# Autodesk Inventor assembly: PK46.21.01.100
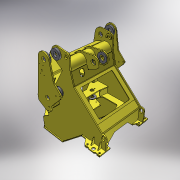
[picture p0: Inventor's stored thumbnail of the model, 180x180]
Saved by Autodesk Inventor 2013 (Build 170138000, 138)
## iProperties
Created: 2005-04
Part Number: PK46.21.01.100
Document SubType Name: Assembly
Designer: salex
Manufacturer: Standard
Standards Organization: Custom
Author: salex
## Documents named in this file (20)
- C:\Product Design Suite 2013 Test Drive\Dynamic Simulation\Workspace\Assy, Chassis, Front\PK46.21.01.100.iam
- C:\Product Design Suite 2013 Test Drive\Dynamic Simulation\Workspace\Assy, Chassis, Front\PK46.21.01.010.iam
- C:\Product Design Suite 2013 Test Drive\Dynamic Simulation\Workspace\Assy, Chassis, Front\PK46.21.01.020.iam
- C:\Product Design Suite 2013 Test Drive\Dynamic Simulation\Workspace\Assy, Chassis, Front\PK46.21.01.030.iam
- C:\Product Design Suite 2013 Test Drive\Dynamic Simulation\Workspace\Assy, Chassis, Front\PK46.21.01.040.iam
- C:\Product Design Suite 2013 Test Drive\Dynamic Simulation\Workspace\Assy, Chassis, Front\PK46.21.01.050.iam
- C:\Product Design Suite 2013 Test Drive\Dynamic Simulation\Workspace\Assy, Chassis, Front\PK46.21.01.060.iam
- C:\Product Design Suite 2013 Test Drive\Dynamic Simulation\Workspace\Assy, Chassis, Front\PK46.21.01.070.iam
- C:\Product Design Suite 2013 Test Drive\Dynamic Simulation\Workspace\Assy, Chassis, Front\PK46.21.01.025.ipt
- C:\Product Design Suite 2013 Test Drive\Dynamic Simulation\Workspace\Assy, Chassis, Front\PK46.21.01.026.ipt
- C:\Product Design Suite 2013 Test Drive\Dynamic Simulation\Workspace\Assy, Chassis, Front\PK46.21.01.027.ipt
- C:\Product Design Suite 2013 Test Drive\Dynamic Simulation\Workspace\Assy, Chassis, Front\PK46.21.01.028.ipt
- C:\Product Design Suite 2013 Test Drive\Dynamic Simulation\Workspace\Assy, Chassis, Front\PK46.21.01.029.ipt
- C:\Product Design Suite 2013 Test Drive\Dynamic Simulation\Workspace\Assy, Chassis, Front\PK46.21.01.031.ipt
- C:\Product Design Suite 2013 Test Drive\Dynamic Simulation\Workspace\Assy, Chassis, Front\027.32.02.621.ipt
- C:\Product Design Suite 2013 Test Drive\Dynamic Simulation\Workspace\Assy, Chassis, Front\PK46.21.01.035.ipt
- C:\Product Design Suite 2013 Test Drive\Dynamic Simulation\Workspace\Assy, Chassis, Front\PK46.21.01.036.ipt
- C:\Product Design Suite 2013 Test Drive\Dynamic Simulation\Workspace\Assy, Chassis, Front\PK46.21.01.032_1.ipt
- C:\Product Design Suite 2013 Test Drive\Dynamic Simulation\Workspace\Assy, Chassis, Front\_PK46.21.01.080.iam
- C:\Product Design Suite 2013 Test Drive\Dynamic Simulation\Workspace\Assy, Chassis, Front\PK46.21.01.080.ipt
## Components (27 placed, 19 different names)
1. PK46.21.01.010:1 [sub-assembly] — Совмещение:1, Совмещение:3, Совмещение:6, Совмещение:9, Угол:1, Совмещение:10, Заподлицо:3, Угол:4, Совмещение:17, Совмещение:18, Совмещение:19, Совмещение:33, Совмещение:34, Совмещение:45, Совмещение:54, Совмещение:61, Совмещение:67, Совмещение:68, Совмещение:73, Угол:8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
2. PK46.21.01.020:1 [sub-assembly] — Совмещение:2, Совмещение:4, Совмещение:6, Совмещение:8, Совмещение:39, Совмещение:40, Совмещение:59, Совмещение:66, Совмещение:69, Совмещение:72, Угол:7
3. PK46.21.01.030:1 [sub-assembly] — Совмещение:17, Совмещение:23, Совмещение:24, Совмещение:25, Касательность:1, Касательность:2, Касательность:3, Совмещение:79, Совмещение:80
4. PK46.21.01.040:1 [sub-assembly] — Совмещение:3, Совмещение:4, Совмещение:7, Заподлицо:2, Совмещение:13, Угол:2, Угол:5
5. PK46.21.01.050:1 [sub-assembly] — Совмещение:1, Совмещение:2, Совмещение:7, Заподлицо:2, Угол:4, Угол:6, Совмещение:55, Совмещение:64, Совмещение:65, Совмещение:70, Совмещение:71
6. PK46.21.01.060:1 [sub-assembly] — Совмещение:9, Заподлицо:1, Угол:1, Совмещение:10, Совмещение:11, Заподлицо:3, Совмещение:16, Совмещение:35, Совмещение:36, Совмещение:37, Совмещение:38, Совмещение:46, Совмещение:50, Совмещение:56, Заподлицо:5, Совмещение:47, Совмещение:75
7. PK46.21.01.070:1 [sub-assembly] — Совмещение:8, Заподлицо:1, Совмещение:11, Совмещение:41, Совмещение:42, Совмещение:43, Совмещение:44, Совмещение:49, Совмещение:53, Совмещение:57, Заподлицо:6
8. _PK46.21.01.080:1 [sub-assembly] — Совмещение:32, Совмещение:54, Совмещение:55, Угол:9
9. PK46.21.01.032_1:1
10. PK46.21.01.032_1:2
11. PK46.21.01.025:1 — Совмещение:45, Совмещение:46, Заподлицо:4, Совмещение:47, Совмещение:48, Совмещение:74
12. PK46.21.01.026:1 — Совмещение:52, Совмещение:53, Совмещение:58, Совмещение:60, Заподлицо:4
13. PK46.21.01.027:1 — Совмещение:49, Совмещение:50, Совмещение:51, Совмещение:52, Совмещение:48
14. PK46.21.01.028:1 — Совмещение:56, Совмещение:58, Совмещение:61
15. PK46.21.01.028:2 — Совмещение:57, Совмещение:59, Совмещение:60
16. PK46.21.01.029:1 — Совмещение:64, Совмещение:67
17. PK46.21.01.029:2 — Совмещение:65, Совмещение:66
18. PK46.21.01.031:1 — Совмещение:68, Заподлицо:5, Совмещение:70
19. PK46.21.01.031:2 — Совмещение:69, Заподлицо:6, Совмещение:71
20. 027.32.02.621:1 — Совмещение:33, Совмещение:36, Совмещение:37
21. 027.32.02.621:2 — Совмещение:34, Совмещение:35, Совмещение:38
22. 027.32.02.621:3 — Совмещение:40, Совмещение:41, Совмещение:44
23. 027.32.02.621:4 — Совмещение:39, Совмещение:42, Совмещение:43
24. PK46.21.01.036:1 — Совмещение:72, Касательность:1, Касательность:2, Угол:7
25. PK46.21.01.035:1 — Совмещение:73, Совмещение:74, Угол:8, Касательность:3, Совмещение:76
26. PK46.21.01.080:1 — Совмещение:78, Угол:9, Совмещение:79, Совмещение:80, Flush:7, Flush:8
27. PK46.21.01.080:2 — Flush:7, Flush:8
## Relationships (83: Mate 64, Flush 8, Angle 8, Tangent 3)
- Совмещение:1 [Mate]: PK46.21.01.010:1 ↔ PK46.21.01.050:1
- Совмещение:2 [Mate]: PK46.21.01.020:1 ↔ PK46.21.01.050:1
- Совмещение:3 [Mate]: PK46.21.01.010:1 ↔ PK46.21.01.040:1
- Совмещение:4 [Mate]: PK46.21.01.020:1 ↔ PK46.21.01.040:1
- Совмещение:6 [Mate]: PK46.21.01.010:1 ↔ PK46.21.01.020:1
- Совмещение:7 [Mate]: PK46.21.01.040:1 ↔ PK46.21.01.050:1
- Совмещение:8 [Mate]: PK46.21.01.020:1 ↔ PK46.21.01.070:1
- Совмещение:9 [Mate]: PK46.21.01.010:1 ↔ PK46.21.01.060:1
- Заподлицо:1 [Flush]: PK46.21.01.060:1 ↔ PK46.21.01.070:1
- Угол:1 [Angle]: PK46.21.01.010:1 ↔ PK46.21.01.060:1
- Совмещение:10 [Mate]: PK46.21.01.010:1 ↔ PK46.21.01.060:1
- Совмещение:11 [Mate]: PK46.21.01.060:1 ↔ PK46.21.01.070:1
- Заподлицо:2 [Flush]: PK46.21.01.040:1 ↔ PK46.21.01.050:1
- Заподлицо:3 [Flush]: PK46.21.01.010:1 ↔ PK46.21.01.060:1
- Совмещение:13 [Mate]: PK46.21.01.040:1
- Угол:2 [Angle]: PK46.21.01.040:1
- Угол:4 [Angle]: PK46.21.01.010:1 ↔ PK46.21.01.050:1
- Угол:5 [Angle]: PK46.21.01.040:1
- Совмещение:16 [Mate]: PK46.21.01.060:1
- Совмещение:17 [Mate]: PK46.21.01.010:1 ↔ PK46.21.01.030:1
- Совмещение:18 [Mate]: PK46.21.01.010:1
- Совмещение:19 [Mate]: PK46.21.01.010:1
- Угол:6 [Angle]: PK46.21.01.050:1
- Совмещение:23 [Mate]: PK46.21.01.030:1
- Совмещение:24 [Mate]: PK46.21.01.030:1
- Совмещение:25 [Mate]: PK46.21.01.030:1
- Совмещение:32 [Mate]: _PK46.21.01.080:1
- Совмещение:33 [Mate]: PK46.21.01.010:1 ↔ 027.32.02.621:1
- Совмещение:34 [Mate]: PK46.21.01.010:1 ↔ 027.32.02.621:2
- Совмещение:35 [Mate]: PK46.21.01.060:1 ↔ 027.32.02.621:2
- Совмещение:36 [Mate]: PK46.21.01.060:1 ↔ 027.32.02.621:1
- Совмещение:37 [Mate]: PK46.21.01.060:1 ↔ 027.32.02.621:1
- Совмещение:38 [Mate]: PK46.21.01.060:1 ↔ 027.32.02.621:2
- Совмещение:39 [Mate]: PK46.21.01.020:1 ↔ 027.32.02.621:4
- Совмещение:40 [Mate]: PK46.21.01.020:1 ↔ 027.32.02.621:3
- Совмещение:41 [Mate]: PK46.21.01.070:1 ↔ 027.32.02.621:3
- Совмещение:42 [Mate]: PK46.21.01.070:1 ↔ 027.32.02.621:4
- Совмещение:43 [Mate]: PK46.21.01.070:1 ↔ 027.32.02.621:4
- Совмещение:44 [Mate]: PK46.21.01.070:1 ↔ 027.32.02.621:3
- Совмещение:45 [Mate]: PK46.21.01.010:1 ↔ PK46.21.01.025:1
- Совмещение:46 [Mate]: PK46.21.01.060:1 ↔ PK46.21.01.025:1
- Совмещение:49 [Mate]: PK46.21.01.070:1 ↔ PK46.21.01.027:1
- Совмещение:50 [Mate]: PK46.21.01.060:1 ↔ PK46.21.01.027:1
- Совмещение:51 [Mate]: PK46.21.01.027:1
- Совмещение:52 [Mate]: PK46.21.01.026:1 ↔ PK46.21.01.027:1
- Совмещение:53 [Mate]: PK46.21.01.070:1 ↔ PK46.21.01.026:1
- Совмещение:54 [Mate]: PK46.21.01.010:1 ↔ _PK46.21.01.080:1
- Совмещение:55 [Mate]: PK46.21.01.050:1 ↔ _PK46.21.01.080:1
- Совмещение:56 [Mate]: PK46.21.01.060:1 ↔ PK46.21.01.028:1
- Совмещение:57 [Mate]: PK46.21.01.070:1 ↔ PK46.21.01.028:2
- Совмещение:58 [Mate]: PK46.21.01.026:1 ↔ PK46.21.01.028:1
- Совмещение:59 [Mate]: PK46.21.01.020:1 ↔ PK46.21.01.028:2
- Совмещение:60 [Mate]: PK46.21.01.026:1 ↔ PK46.21.01.028:2
- Совмещение:61 [Mate]: PK46.21.01.010:1 ↔ PK46.21.01.028:1
- Совмещение:64 [Mate]: PK46.21.01.050:1 ↔ PK46.21.01.029:1
- Совмещение:65 [Mate]: PK46.21.01.050:1 ↔ PK46.21.01.029:2
- Совмещение:66 [Mate]: PK46.21.01.020:1 ↔ PK46.21.01.029:2
- Совмещение:67 [Mate]: PK46.21.01.010:1 ↔ PK46.21.01.029:1
- Совмещение:68 [Mate]: PK46.21.01.010:1 ↔ PK46.21.01.031:1
- Совмещение:69 [Mate]: PK46.21.01.020:1 ↔ PK46.21.01.031:2
- Заподлицо:5 [Flush]: PK46.21.01.060:1 ↔ PK46.21.01.031:1
- Заподлицо:6 [Flush]: PK46.21.01.070:1 ↔ PK46.21.01.031:2
- Совмещение:70 [Mate]: PK46.21.01.050:1 ↔ PK46.21.01.031:1
- Совмещение:71 [Mate]: PK46.21.01.050:1 ↔ PK46.21.01.031:2
- Заподлицо:4 [Flush]: PK46.21.01.025:1 ↔ PK46.21.01.026:1
- Совмещение:47 [Mate]: PK46.21.01.060:1 ↔ PK46.21.01.025:1
- Совмещение:48 [Mate]: PK46.21.01.025:1 ↔ PK46.21.01.027:1
- Совмещение:72 [Mate]: PK46.21.01.020:1 ↔ PK46.21.01.036:1
- Касательность:1 [Tangent]: PK46.21.01.030:1 ↔ PK46.21.01.036:1
- Касательность:2 [Tangent]: PK46.21.01.030:1 ↔ PK46.21.01.036:1
- Угол:7 [Angle]: PK46.21.01.020:1 ↔ PK46.21.01.036:1
- Совмещение:73 [Mate]: PK46.21.01.010:1 ↔ PK46.21.01.035:1
- Совмещение:74 [Mate]: PK46.21.01.025:1 ↔ PK46.21.01.035:1
- Угол:8 [Angle]: PK46.21.01.010:1 ↔ PK46.21.01.035:1
- Касательность:3 [Tangent]: PK46.21.01.030:1 ↔ PK46.21.01.035:1
- Совмещение:75 [Mate]: PK46.21.01.060:1
- Совмещение:76 [Mate]: PK46.21.01.035:1
- Совмещение:78 [Mate]: PK46.21.01.010:1 ↔ PK46.21.01.080:1
- Угол:9 [Angle]: _PK46.21.01.080:1 ↔ PK46.21.01.080:1
- Совмещение:79 [Mate]: PK46.21.01.030:1 ↔ PK46.21.01.080:1
- Совмещение:80 [Mate]: PK46.21.01.030:1 ↔ PK46.21.01.080:1
- Flush:7: PK46.21.01.080:1 ↔ PK46.21.01.080:2
- Flush:8: PK46.21.01.080:1 ↔ PK46.21.01.080:2
